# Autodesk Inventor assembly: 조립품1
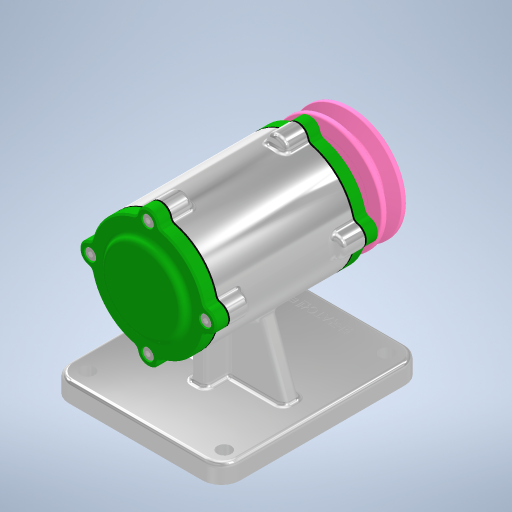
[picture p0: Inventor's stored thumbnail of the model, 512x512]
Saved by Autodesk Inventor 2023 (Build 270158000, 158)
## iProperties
Created: 2023-08
Part Number: 조립품1
Document SubType Name: Assembly
Designer: asung
Author: asung
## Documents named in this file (12)
- C:\Users\asung\Desktop\730808V1006\조립품1.iam
- C:\Users\asung\Desktop\730808V1006\본체.ipt
- C:\Users\asung\Desktop\730808V1006\앞커버.ipt
- C:\Users\asung\Desktop\730808V1006\개스킷.ipt
- C:\Users\asung\Desktop\730808V1006\뒤커버.ipt
- C:\Users\asung\Desktop\730808V1006\베어링 6204.ipt
- C:\Users\asung\Desktop\730808V1006\축.ipt
- C:\Users\asung\Desktop\730808V1006\오일 실.ipt
- C:\Users\asung\Desktop\730808V1006\볼트 M4 x 12.ipt
- C:\Users\asung\Desktop\730808V1006\키 4 x 4.ipt
- C:\Users\asung\Desktop\730808V1006\V-벨트풀리.ipt
- C:\Users\asung\Desktop\730808V1006\너트 M12 x 1.25.ipt
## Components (8 placed, 6 different names)
1. 개스킷:1
2. 개스킷:2
3. KS B 2023 6204 - 20 x 47 x 14:1
4. KS B 2023 6204 - 20 x 47 x 14:2
5. KS B 2804 D D - 20 32 8:1
6. KS B 1311 (I) 4 x 4 x 12:1
7. V-벨트풀리:1
8. KS B 1012 클래스 1 일반 - 미터 M12x1.25:1
